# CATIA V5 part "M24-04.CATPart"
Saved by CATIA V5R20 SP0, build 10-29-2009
Part number: M24-04
Revision: ANY
Definition: UNKNOWN
Nomenclature: M24-04
Source: Unknown
Bounding box of the stored display mesh (mm): x -52.5 to 52.5, y -52.5 to 52.5, z 0 to 10
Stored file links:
  C:\Users\Utente\Desktop\IO LAVORO\3D X SITO CF\X 3D SITO CF 27-09-2020\740T\740T-24\M24-04.CATPart
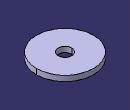
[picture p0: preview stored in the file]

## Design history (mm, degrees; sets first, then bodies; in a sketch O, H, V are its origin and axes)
Body1 "NONE" (main body)
  Solid1: solid without history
